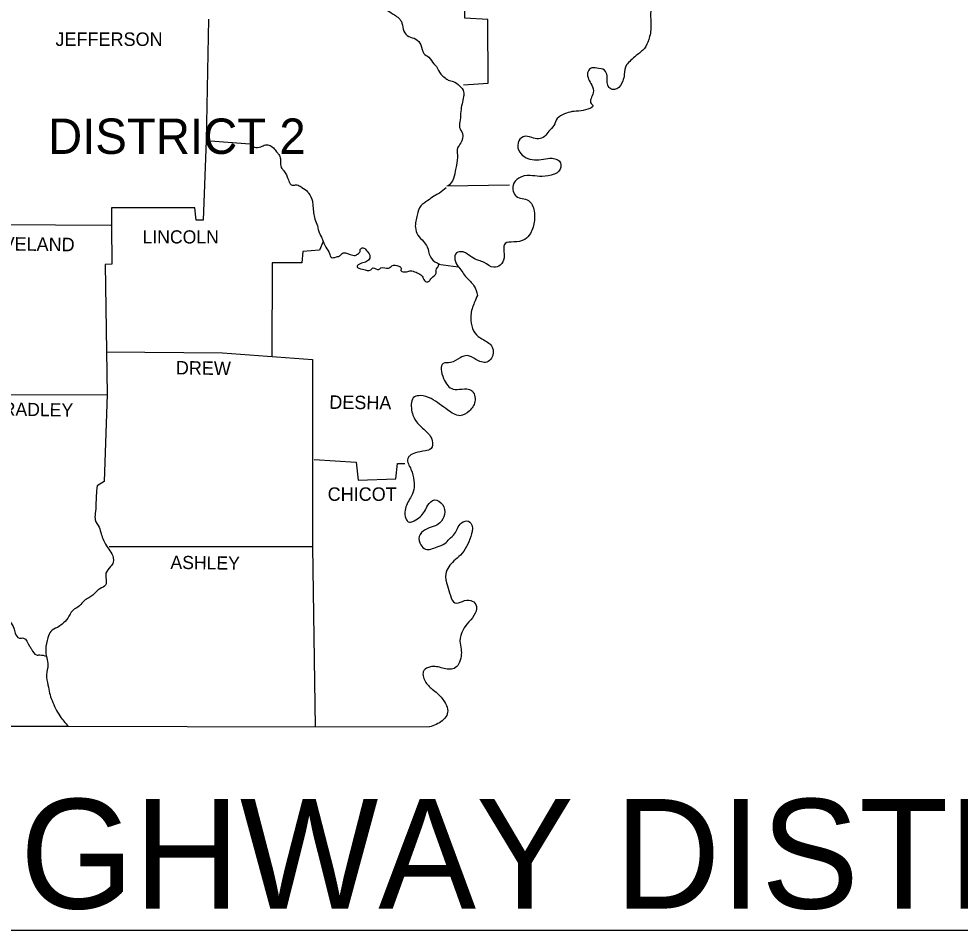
# Model space of a CAD drawing. Extents: x -17742 to 32032, y -17264 to 5867.
# Drawn here: x -16002 to -14349, y -10461 to -8859 of the extents above; entities that cross this region are included whole.
import ezdxf

# ---------------------------------------------------------------- set-up
doc = ezdxf.new("R2010")
doc.units = 0
for name, color, linetype in [('1', 7, 'Continuous'), ('2', 7, 'Continuous'), ('3', 7, 'Continuous'), ('R_Annotation', 7, 'Continuous')]:
    doc.layers.add(name, color=color, linetype=linetype)

msp = doc.modelspace()

# ---------------------------------------------------------------- linework, layer by layer
at = {"layer": '1'}
for p, q in [((-15250.6, -9152.5), (-15140.6, -9150.8)), ((-17741.9, -10460.7), (-14228.8, -10460.7))]:
    msp.add_line(p, q, dxfattribs=at)
for points in [[(-15220.9, -8974.7), (-15178, -8972), (-15178.6, -8860.2), (-15218.7, -8857.5), (-15216.5, -8639), (-15251.2, -8634), (-15252.3, -8487.1), (-14782.8, -8483.8)], [(-15668.9, -8859.7), (-15673.3, -9072.7), (-15596.8, -9078.7)], [(-15673.3, -9072.7), (-15678.3, -9212.5), (-15690.9, -9212.5), (-15693.1, -9191), (-15839.5, -9191), (-15839.5, -9221.8)], [(-15467.5, -9250.4), (-15474.1, -9265.3), (-15503.3, -9268.1), (-15504.9, -9287.9), (-15557.2, -9287.9), (-15557.7, -9452.4)], [(-15848.9, -9444.2), (-15644.7, -9445.8), (-15486.2, -9457.9)], [(-15486.2, -9457.9), (-15486.2, -9787), (-15481.8, -10103.5)], [(-16096, -9519.6), (-15847.2, -9519)], [(-15483.4, -9633.5), (-15409.7, -9637.9), (-15406.4, -9669.8), (-15339.8, -9667.6), (-15337.1, -9640.6), (-15324.4, -9640.6)], [(-15843.9, -9786.5), (-15486.2, -9786.5)], [(-16558.1, -10101.4), (-15280.9, -10103.5)]]:
    msp.add_lwpolyline(points, dxfattribs=at)
for points in [[(-14817.5, -8617), (-14830.2, -8632.9), (-14848.9, -8623), (-14848.9, -8609.8), (-14846.1, -8596.1), (-14852.7, -8587.3), (-14864.3, -8591.1), (-14864.3, -8608.2), (-14865.4, -8624.7), (-14868.7, -8648.4), (-14861, -8655.5), (-14843.4, -8657.7), (-14830.7, -8661), (-14823, -8673.7), (-14823.6, -8689.1), (-14829.6, -8703.9), (-14838.4, -8716), (-14852.2, -8720.5), (-14863.2, -8713.3), (-14867.6, -8699), (-14872.6, -8686.3), (-14881.9, -8677), (-14891.8, -8687.4), (-14894, -8706.7), (-14893.5, -8723.2), (-14893.5, -8745.8), (-14879.2, -8760.6), (-14870.4, -8777.7), (-14873.1, -8793.1), (-14883.6, -8811.3), (-14888, -8827.2), (-14892.4, -8848.7), (-14891.8, -8872.3), (-14895.7, -8895.5), (-14903.4, -8910.9), (-14917.7, -8923.5), (-14927, -8931.8), (-14934.7, -8940), (-14938.6, -8956.6), (-14941.3, -8968.1), (-14951.8, -8981.9), (-14960.1, -8983), (-14966.7, -8977.5), (-14968.9, -8968.1), (-14968.9, -8958.8), (-14973.3, -8949.4), (-14987, -8945.5), (-14998, -8946.1), (-15003, -8953.8), (-14995.8, -8975.3), (-14993.1, -8989), (-14996.9, -9007.7), (-14994.7, -9009.9), (-15014.5, -9020.4), (-15030.5, -9022), (-15043.7, -9025.9), (-15056.4, -9034.2), (-15062.4, -9046.3), (-15071.2, -9056.2), (-15078.9, -9065.5), (-15089.4, -9069.9), (-15101, -9067.7), (-15116.4, -9066.1), (-15125.2, -9077.1), (-15122.4, -9093), (-15112, -9102.4), (-15096.5, -9106.8), (-15080.6, -9105.7), (-15065.2, -9104), (-15050.9, -9111.8), (-15053.6, -9126.6), (-15067.4, -9133.8), (-15087.7, -9136), (-15104.3, -9134.3), (-15124.1, -9138.7), (-15134, -9151.4), (-15128.5, -9170.6), (-15107, -9178.3), (-15097.1, -9196.5), (-15096.5, -9213.6), (-15103.7, -9236.1), (-15113.6, -9246.6), (-15132.9, -9251), (-15147.7, -9253.7), (-15149.9, -9279.1), (-15156.5, -9291.7), (-15168.1, -9295.6), (-15184.6, -9287.3), (-15194.5, -9283.5), (-15206.6, -9278), (-15222, -9268.6), (-15233.6, -9270.3), (-15230.3, -9294.5), (-15229.2, -9295.6), (-15216, -9313.7), (-15202.8, -9328), (-15196.7, -9345.1)], [(-15387.7, -8794.2), (-15386, -8816.8), (-15372.8, -8820.1), (-15367.3, -8826.1), (-15364.6, -8838.8), (-15355.2, -8844.3), (-15342.6, -8852), (-15334.9, -8857.5), (-15329.3, -8866.3), (-15326, -8880.6), (-15317.2, -8890), (-15305.1, -8894.4), (-15296.3, -8904.8), (-15290.8, -8919.7), (-15282, -8926.3), (-15273.2, -8937.8), (-15268.8, -8942.8), (-15261.1, -8956), (-15253.4, -8962.6), (-15247.9, -8966.5), (-15239.1, -8969.2), (-15228.1, -8976.4), (-15220.9, -8987.4), (-15220.9, -8995.6), (-15223.7, -9008.3), (-15225.9, -9021.5), (-15227, -9036.4), (-15228.1, -9049.6), (-15223.1, -9060.6), (-15225.9, -9077.1), (-15231.4, -9085.9), (-15231.9, -9098), (-15233.6, -9116.2), (-15235.8, -9126.6), (-15240.7, -9143.7), (-15247.9, -9152.5)], [(-15596.8, -9078.7), (-15588.6, -9084.2), (-15577, -9083.7), (-15569.3, -9080.4), (-15563.2, -9080.9), (-15555, -9085.9), (-15549.5, -9092.5), (-15545.6, -9097.4), (-15542.9, -9105.1), (-15542.9, -9112.3), (-15540.1, -9122.2), (-15536.8, -9126.1), (-15532.4, -9133.2), (-15529.7, -9139.8), (-15528, -9144.2), (-15522, -9151.4), (-15516.5, -9150.8), (-15511.5, -9151.4), (-15504.9, -9155.2), (-15495, -9162.9), (-15493.4, -9165.1), (-15486.7, -9179.4), (-15485.6, -9188.3), (-15484.5, -9199.8), (-15482.3, -9210.8), (-15477.9, -9222.9), (-15475.7, -9231.2), (-15470.8, -9242.7), (-15467.5, -9250.4), (-15463.1, -9260.3), (-15456.5, -9271.4), (-15453.7, -9278), (-15444.4, -9277.4), (-15437.8, -9274.7), (-15432.8, -9270.3), (-15426.8, -9270.8), (-15420.2, -9273), (-15411.4, -9274.7), (-15405.8, -9271.4), (-15403.1, -9269.2), (-15402.5, -9264.2), (-15397.6, -9261.5), (-15392.1, -9265.3), (-15386, -9274.1), (-15386, -9279.6), (-15388.2, -9282.9), (-15395.4, -9287.3), (-15405.3, -9290.6), (-15408, -9294.5), (-15398.7, -9298.9), (-15383.8, -9300), (-15380, -9296.7), (-15370.1, -9299.4), (-15366.2, -9296.7), (-15353, -9297.2), (-15347, -9292.8), (-15334.9, -9293.4), (-15331, -9296.1), (-15331, -9301.1), (-15321.1, -9303.3), (-15313.9, -9301.6), (-15304.6, -9304.4), (-15296.3, -9308.8), (-15291.9, -9314.8), (-15286.4, -9321.4), (-15281.5, -9319.8), (-15277.6, -9314.8), (-15269.4, -9306), (-15269.4, -9300.5), (-15267.2, -9296.7), (-15264.4, -9291.2)], [(-15251.7, -9155.8), (-15263.3, -9165.1), (-15273.2, -9170.6), (-15283.7, -9178.3), (-15296.3, -9187.7), (-15302.4, -9203.7), (-15305.7, -9225.7), (-15301.3, -9238.9), (-15291.4, -9250.4), (-15284.8, -9259.8), (-15279.8, -9276.3), (-15267.7, -9287.9), (-15263.9, -9289.5)], [(-15196.7, -9345.1), (-15202.2, -9357.8), (-15208.3, -9379.8), (-15206.6, -9398.5), (-15198.4, -9414.4), (-15185.2, -9423.3), (-15170.8, -9435.9), (-15171.9, -9455.2), (-15180.2, -9462.3), (-15199.5, -9457.4), (-15214.3, -9450.8), (-15227, -9454.6), (-15244, -9462.9), (-15256.7, -9464.5), (-15256.2, -9490.9), (-15239.1, -9509.7), (-15224.2, -9509.7), (-15207.2, -9511.9), (-15201.1, -9531.7), (-15211, -9548.2), (-15227.5, -9556.4), (-15248.4, -9546.5), (-15263.3, -9536.1), (-15278.2, -9526.2), (-15296.9, -9521.2), (-15307.3, -9523.4), (-15312.3, -9546.5), (-15303.5, -9567.4), (-15289.2, -9581.8), (-15276, -9600.5), (-15278.2, -9614.2), (-15288.1, -9618.1), (-15305.7, -9621.9), (-15316.1, -9627.4), (-15318.9, -9631.8), (-15313.4, -9650.6), (-15308.4, -9670.9), (-15308.4, -9686.3), (-15314.5, -9700.6), (-15323.8, -9722.6), (-15322.7, -9737), (-15316.1, -9743.6), (-15307.9, -9741.4), (-15296.9, -9733.7), (-15289.7, -9724.8), (-15283.7, -9713.8), (-15272.1, -9704.5), (-15257.8, -9712.7), (-15254.5, -9729.8), (-15262.8, -9744.7), (-15274.3, -9751.3), (-15288.6, -9756.8), (-15299.1, -9768.9), (-15296.3, -9783.2), (-15288.1, -9790.9), (-15267.7, -9787), (-15253.9, -9781), (-15246.2, -9773.3), (-15236.9, -9763.9), (-15231.9, -9754.6), (-15224.8, -9744.7), (-15212.1, -9741.9), (-15206.1, -9750.2), (-15208.3, -9768.9), (-15216, -9786.5), (-15226.4, -9801.3), (-15238, -9811.8), (-15252.3, -9834.4), (-15249.5, -9855.3), (-15244, -9872.3), (-15236.3, -9885.6), (-15223.1, -9882.8), (-15208.3, -9881.1), (-15199.5, -9888.3), (-15200.6, -9903.7), (-15211.6, -9918.6), (-15222, -9932.9), (-15227.5, -9952.7), (-15225.3, -9966.5), (-15225.3, -9979.1), (-15229.7, -9992.9), (-15237.4, -10000.6), (-15257.8, -10000), (-15279.3, -9997.8), (-15290.8, -10004.4), (-15288.6, -10023.1), (-15276, -10036.9), (-15267.2, -10044.1), (-15254.5, -10059.5), (-15249, -10072.1), (-15250.6, -10083.1), (-15258.4, -10092.5), (-15280.9, -10103.5)], [(-16413.5, -9806.9), (-16404.7, -9800.8), (-16396.5, -9797.5), (-16388.2, -9799.1), (-16379.4, -9800.2), (-16371.7, -9799.1), (-16361.8, -9800.8), (-16353.6, -9805.8), (-16344.2, -9809.6), (-16334.8, -9809.6), (-16326.6, -9809.6), (-16319.4, -9814.6), (-16306.2, -9814), (-16295.2, -9809.6), (-16284.2, -9806.3), (-16269.4, -9804.6), (-16256.1, -9814), (-16246.8, -9821.7), (-16239.1, -9830.5), (-16233.6, -9840.4), (-16227.5, -9845.9), (-16217.6, -9849.8), (-16209.9, -9851.4), (-16200.6, -9854.2), (-16195.6, -9856.4), (-16191.2, -9866.8), (-16184, -9881.1), (-16170.3, -9886.1), (-16153.2, -9879.5), (-16139.5, -9875.6), (-16129.6, -9872.3), (-16123.5, -9870.1), (-16118, -9869.6), (-16119.7, -9868.5), (-16113.1, -9866.8), (-16107, -9871.2), (-16103.1, -9877.3), (-16096.5, -9886.1), (-16090.5, -9893.8), (-16084.4, -9896.6), (-16078.4, -9893.3), (-16070.1, -9896), (-16063, -9898.8), (-16054.7, -9901), (-16047.6, -9901.5), (-16038.2, -9903.7), (-16031, -9907.6), (-16024.4, -9911.4), (-16017.8, -9918.6), (-16011.2, -9929.6), (-16009, -9938.4), (-16001.3, -9947.2), (-15994.2, -9947.2), (-15983.7, -9961.5), (-15979.9, -9967), (-15971.6, -9976.9), (-15965.6, -9976.9), (-15954, -9979.1)]]:
    msp.add_spline(points, degree=3, dxfattribs=at)
at = {"layer": '3'}
msp.add_line((-15265.5, -9290.1), (-15230.8, -9294.5), dxfattribs=at)
at = {"layer": 'R_Annotation'}
for points in [[(-16115.8, -9225.1), (-16035.5, -9220.2), (-15840.6, -9221.3), (-15839.5, -9221.3), (-15839, -9290.1), (-15850.5, -9290.6), (-15847.2, -9519), (-15852.7, -9672), (-15864.8, -9679.7)], [(-15915.6, -10102.4), (-16558.1, -10101.3)]]:
    msp.add_lwpolyline(points, dxfattribs=at)
msp.add_spline([(-15864.8, -9679.7), (-15866.5, -9696.8), (-15867, -9712.7), (-15868.1, -9728.2), (-15868.1, -9739.7), (-15861.5, -9752.4), (-15857.7, -9764.5), (-15853.8, -9774.9), (-15846.1, -9788.7), (-15839, -9799.1), (-15836.8, -9814), (-15841.2, -9821.7), (-15849.4, -9833.3), (-15850, -9854.2), (-15859.9, -9860.8), (-15872.5, -9871.8), (-15879.7, -9876.7), (-15887.4, -9881.7), (-15895.7, -9890.5), (-15907.8, -9898.8), (-15916.6, -9912.5), (-15926.5, -9923), (-15934.7, -9928.5), (-15946.3, -9935.6), (-15951.2, -9946.6), (-15955.1, -9967), (-15953.4, -9981.9), (-15951.2, -9995.1), (-15954, -10011.6), (-15951.2, -10029.7), (-15948.5, -10044.1), (-15944.1, -10056.7), (-15938, -10071), (-15930.3, -10084.2), (-15915.6, -10102.4)], degree=3, dxfattribs=at)

# ---------------------------------------------------------------- texts
at = {"layer": '2'}
for s, height, p in [('JEFFERSON', 23.67, (-15938, -8906.5)), ('LINCOLN', 23.11, (-15785, -9253.7)), ('CHICOT', 23.67, (-15459.8, -9706.1)), ('ARKANSAS HIGHWAY DISTRICT 7', 192.623, (-17732.4, -10422.7))]:
    msp.add_text(s, height=height, dxfattribs=at).set_placement(p)
for s, height, rotation, p in [('CLEVELAND', 23.67, 359.3377, (-16092.7, -9265.3)), ('DREW', 23.66, 359.2258, (-15726.7, -9483.8)), ('DESHA', 23.66, 359.3704, (-15457, -9544.3)), ('BRADLEY', 23.11, 359.1449, (-16051.4, -9555.9)), ('ASHLEY', 23.11, 359.2361, (-15736.1, -9825.6))]:
    msp.add_text(s, height=height, rotation=rotation, dxfattribs=at).set_placement(p)
at = {"layer": '3'}
msp.add_text('DISTRICT 2', height=62.19, dxfattribs=at).set_placement((-15951.2, -9096.3))

doc.saveas('drawing.dxf')
